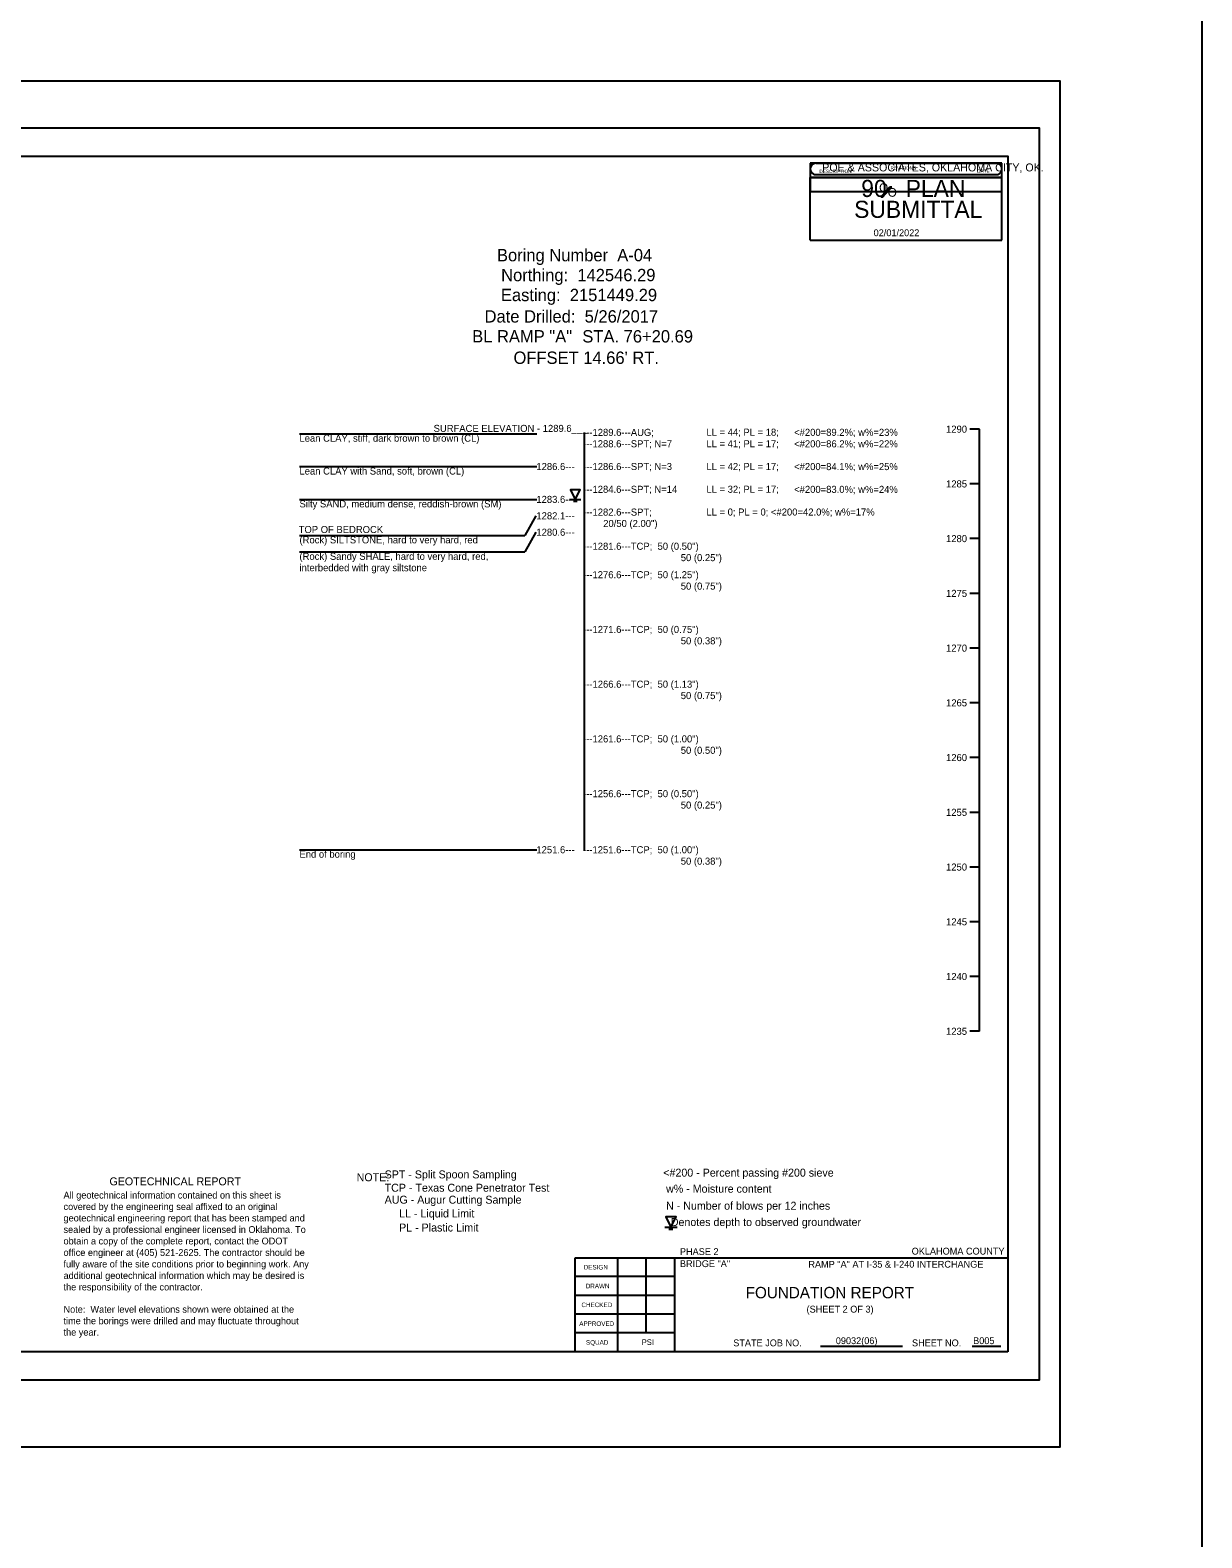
# Model space of a CAD drawing. Extents: x 2150161.5 to 2150203.1, y 143779.5 to 143868.5.
# Drawn here: x 2150182.49 to 2150203.07, y 143808.09 to 143834.58 of the extents above; entities that cross this region are included whole.
import ezdxf

# ---------------------------------------------------------------- set-up
doc = ezdxf.new("R2010")
doc.units = 0
for name, color, linetype in [('Default', 7, 'Continuous'), ('S', 7, 'Continuous'), ('SHT_Plot_Shape_Full', 7, 'Continuous'), ('SHT_Plot_Shape_Half', 7, 'Continuous'), ('SHT_Sheet_Border', 7, 'Continuous'), ('SHT_Stamp_90_Submit', 7, 'Continuous'), ('SHT_Stamp_Rev_Block', 7, 'Continuous'), ('SHT_Standard_Sheet_Lines', 7, 'Continuous'), ('SHT_Standard_Sheet_Txt', 7, 'Continuous'), ('T', 7, 'Continuous'), ('T-Title', 7, 'Continuous'), ('Text', 7, 'Continuous')]:
    doc.layers.add(name, color=color, linetype=linetype)

# ---------------------------------------------------------------- blocks, each defined once
blk = doc.blocks.new('DGRFC_WTLEV1')
at = {"layer": 'Default'}
for points in [[(-0.0127, 0), (0.0127, 0)], [(0, 0), (0.0106, 0.0212), (-0.0106, 0.0212), (0, 0)], [(-0.0042, -0.0042), (0.0042, -0.0042)]]:
    blk.add_lwpolyline(points, dxfattribs=at)

msp = doc.modelspace()

# ---------------------------------------------------------------- linework, layer by layer
at = {"layer": 'Default'}
for p, q in [((2150199.164, 143816.992), (2150199.164, 143827.569)), ((2150191.371, 143826.046), (2150191.182, 143825.702)), ((2150191.371, 143825.758), (2150191.182, 143825.414))]:
    msp.add_line(p, q, dxfattribs=at)
for points in [[(2150199.164, 143827.569), (2150198.997, 143827.569)], [(2150187.222, 143827.489), (2150191.388, 143827.489)], [(2150192.221, 143827.507), (2150192.221, 143820.172)], [(2150187.222, 143826.912), (2150191.388, 143826.912)], [(2150199.164, 143826.607), (2150198.997, 143826.607)], [(2150187.222, 143826.335), (2150191.388, 143826.335)], [(2150187.222, 143825.702), (2150191.182, 143825.702)], [(2150199.164, 143825.646), (2150198.997, 143825.646)], [(2150187.222, 143825.414), (2150191.182, 143825.414)], [(2150199.164, 143824.684), (2150198.997, 143824.684)], [(2150199.164, 143823.723), (2150198.997, 143823.723)], [(2150199.164, 143822.761), (2150198.997, 143822.761)], [(2150199.164, 143821.8), (2150198.997, 143821.8)], [(2150199.164, 143820.838), (2150198.997, 143820.838)], [(2150187.222, 143820.181), (2150191.388, 143820.181)], [(2150199.164, 143819.877), (2150198.997, 143819.877)], [(2150199.164, 143818.915), (2150198.997, 143818.915)], [(2150199.164, 143818.915), (2150198.997, 143818.915)], [(2150199.164, 143817.954), (2150198.997, 143817.954)], [(2150199.164, 143817.954), (2150198.997, 143817.954)], [(2150199.164, 143816.992), (2150198.997, 143816.992)], [(2150199.164, 143816.992), (2150198.997, 143816.992)]]:
    msp.add_lwpolyline(points, dxfattribs=at)
at = {"layer": 'S'}
msp.add_lwpolyline([(2150161.53, 143868.477), (2150203.071, 143868.477), (2150203.071, 143779.536), (2150161.53, 143779.536)], close=True, dxfattribs=at)
at = {"layer": 'SHT_Plot_Shape_Full'}
msp.add_lwpolyline([(2150164.575, 143833.688), (2150200.575, 143833.688), (2150200.575, 143809.688), (2150164.575, 143809.688)], close=True, dxfattribs=at)
at = {"layer": 'SHT_Plot_Shape_Half'}
msp.add_lwpolyline([(2150166.212, 143832.863), (2150200.212, 143832.863), (2150200.212, 143810.863), (2150166.212, 143810.863)], close=True, dxfattribs=at)
at = {"layer": 'SHT_Sheet_Border'}
for p, q in [((2150192.062, 143811.363), (2150192.062, 143813.013)), ((2150192.062, 143813.013), (2150199.662, 143813.013)), ((2150193.812, 143811.363), (2150193.812, 143813.014))]:
    msp.add_line(p, q, dxfattribs=at)
msp.add_lwpolyline([(2150199.662, 143811.363), (2150168.162, 143811.363), (2150168.162, 143832.363), (2150199.662, 143832.363)], close=True, dxfattribs=at)
at = {"layer": 'SHT_Stamp_90_Submit'}
for p, q in [((2150196.293, 143832.239), (2150199.459, 143832.239)), ((2150196.193, 143831.989), (2150199.559, 143831.989)), ((2150196.193, 143830.889), (2150196.193, 143831.989)), ((2150196.293, 143832.039), (2150199.459, 143832.039)), ((2150197.437, 143831.65), (2150197.592, 143831.823)), ((2150197.454, 143831.65), (2150197.61, 143831.823)), ((2150197.459, 143831.65), (2150197.615, 143831.823)), ((2150197.467, 143831.65), (2150197.623, 143831.823)), ((2150197.592, 143831.823), (2150197.623, 143831.823)), ((2150199.559, 143830.889), (2150199.559, 143831.989)), ((2150197.437, 143831.65), (2150197.467, 143831.65)), ((2150196.193, 143830.889), (2150199.559, 143830.889))]:
    msp.add_line(p, q, dxfattribs=at)
for centre, start, end in [((2150196.294, 143832.139), 89.9952, 270), ((2150199.46, 143832.139), 270, 90.0048)]:
    msp.add_arc(centre, 0.1, start, end, dxfattribs=at)
at = {"layer": 'SHT_Stamp_Rev_Block'}
for p, q in [((2150196.194, 143832.239), (2150196.194, 143831.739)), ((2150199.559, 143832.239), (2150196.194, 143832.239)), ((2150199.559, 143831.739), (2150199.559, 143832.239)), ((2150199.559, 143831.989), (2150196.194, 143831.989)), ((2150199.559, 143831.739), (2150196.194, 143831.739))]:
    msp.add_line(p, q, dxfattribs=at)
at = {"layer": 'SHT_Standard_Sheet_Lines'}
for p, q in [((2150192.812, 143811.363), (2150192.812, 143813.014)), ((2150193.312, 143811.693), (2150193.312, 143813.014)), ((2150196.373, 143811.459), (2150197.813, 143811.459)), ((2150199.038, 143811.459), (2150199.54, 143811.459))]:
    msp.add_line(p, q, dxfattribs=at)
for points in [[(2150193.812, 143812.683), (2150192.062, 143812.683)], [(2150193.812, 143812.353), (2150192.062, 143812.353)], [(2150193.812, 143812.023), (2150192.062, 143812.023)], [(2150193.812, 143811.693), (2150192.062, 143811.693)]]:
    msp.add_lwpolyline(points, dxfattribs=at)

# ---------------------------------------------------------------- block references
at = {"layer": 'Default'}
for p, xscale, yscale in [((2150192.066, 143826.335), 7.873999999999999, 7.873999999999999), ((2150193.745, 143813.553), 8.503919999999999, 8.503919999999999)]:
    msp.add_blockref('DGRFC_WTLEV1', p, dxfattribs=dict(at, xscale=xscale, yscale=yscale))

# ---------------------------------------------------------------- texts
for s, height, p in [('Boring Number  A-04', 0.217, (2150190.691, 143830.517)), ('Northing:  142546.29', 0.217, (2150190.764, 143830.167)), ('Easting:  2151449.29', 0.217, (2150190.76, 143829.817)), ('Date Drilled:  5/26/2017', 0.217, (2150190.473, 143829.441)), ('BL RAMP "A" ', 0.217, (2150190.256, 143829.091)), ('STA. 76+20.69', 0.217, (2150192.19, 143829.091)), ("OFFSET 14.66' RT.", 0.217, (2150190.981, 143828.715)), ('SURFACE ELEVATION - 1289.6___', 0.124, (2150189.578, 143827.52)), ('---1289.6---AUG;', 0.124, (2150192.203, 143827.45)), ('LL = 44; PL = 18;', 0.124, (2150194.369, 143827.453)), ('<#200=89.2%; w%=23%', 0.124, (2150195.91, 143827.451)), ('Lean CLAY, stiff, dark brown to brown (CL)', 0.124, (2150187.222, 143827.348)), ('---1288.6---SPT; N=7', 0.124, (2150192.203, 143827.25)), ('LL = 41; PL = 17;', 0.124, (2150194.369, 143827.251)), ('<#200=86.2%; w%=22%', 0.124, (2150195.91, 143827.249)), ('Lean CLAY with Sand, soft, brown (CL)', 0.124, (2150187.222, 143826.771)), ('1286.6---', 0.124, (2150191.383, 143826.85)), ('---1286.6---SPT; N=3', 0.124, (2150192.203, 143826.85)), ('LL = 42; PL = 17;', 0.124, (2150194.369, 143826.851)), ('<#200=84.1%; w%=25%', 0.124, (2150195.91, 143826.849)), ('---1284.6---SPT; N=14', 0.124, (2150192.203, 143826.45)), ('LL = 32; PL = 17;', 0.124, (2150194.369, 143826.451)), ('<#200=83.0%; w%=24%', 0.124, (2150195.91, 143826.449)), ('Silty SAND, medium dense, reddish-brown (SM)', 0.124, (2150187.222, 143826.194)), ('1283.6---', 0.124, (2150191.383, 143826.273)), ('1282.1---', 0.124, (2150191.383, 143825.985)), ('---1282.6---SPT;', 0.124, (2150192.203, 143826.05)), ('20/50 (2.00")', 0.124, (2150192.557, 143825.85)), ('LL = 0; PL = 0; <#200=42.0%%%; w%%%=17%%%', 0.124, (2150194.369, 143826.051)), ('TOP OF BEDROCK', 0.124, (2150187.208, 143825.744)), ('1280.6---', 0.124, (2150191.383, 143825.696)), ('(Rock) SILTSTONE, hard to very hard, red', 0.124, (2150187.222, 143825.562)), ('---1281.6---TCP;  50 (0.50")', 0.124, (2150192.203, 143825.45)), ('(Rock) Sandy SHALE, hard to very hard, red,', 0.124, (2150187.222, 143825.273)), ('interbedded with gray siltstone', 0.124, (2150187.222, 143825.073)), ('50 (0.25")', 0.124, (2150193.919, 143825.25)), ('---1276.6---TCP;  50 (1.25")', 0.124, (2150192.203, 143824.95)), ('50 (0.75")', 0.124, (2150193.919, 143824.75)), ('---1271.6---TCP;  50 (0.75")', 0.124, (2150192.203, 143823.989)), ('50 (0.38")', 0.124, (2150193.919, 143823.789)), ('---1266.6---TCP;  50 (1.13")', 0.124, (2150192.203, 143823.027)), ('50 (0.75")', 0.124, (2150193.919, 143822.827)), ('---1261.6---TCP;  50 (1.00")', 0.124, (2150192.203, 143822.066)), ('50 (0.50")', 0.124, (2150193.919, 143821.866)), ('---1256.6---TCP;  50 (0.50")', 0.124, (2150192.203, 143821.104)), ('50 (0.25")', 0.124, (2150193.919, 143820.904)), ('End of boring', 0.124, (2150187.222, 143820.041)), ('1251.6---', 0.124, (2150191.383, 143820.119)), ('---1251.6---TCP;  50 (1.00")', 0.124, (2150192.203, 143820.119)), ('50 (0.38")', 0.124, (2150193.919, 143819.919))]:
    msp.add_text(s, height=height, dxfattribs=at).set_placement(p)
for s, p in [('1290', (2150198.578, 143827.507)), ('1285', (2150198.578, 143826.545)), ('1280', (2150198.578, 143825.584)), ('1275', (2150198.578, 143824.622)), ('1270', (2150198.578, 143823.661)), ('1265', (2150198.578, 143822.699)), ('1260', (2150198.578, 143821.738)), ('1255', (2150198.578, 143820.776)), ('1250', (2150198.578, 143819.815)), ('1245', (2150198.578, 143818.853)), ('1240', (2150198.578, 143817.892)), ('1235', (2150198.578, 143816.93))]:
    msp.add_text(s, height=0.124, rotation=0.0001, dxfattribs=at).set_placement(p)
at = {"layer": 'SHT_Stamp_90_Submit'}
for s, height, p in [('POE & ASSOCIATES, OKLAHOMA CITY, OK.', 0.14, (2150196.403, 143832.096)), ('90   PLAN', 0.3, (2150197.089, 143831.647)), ('O', 0.153, (2150197.402, 143831.735)), ('O', 0.153, (2150197.554, 143831.651)), ('SUBMITTAL', 0.3, (2150196.964, 143831.28)), ('02/01/2022', 0.12, (2150197.306, 143830.958))]:
    msp.add_text(s, height=height, dxfattribs=at).set_placement(p)
at = {"layer": 'SHT_Stamp_Rev_Block'}
for s, height, p in [('DESCRIPTION', 0.05999, (2150196.353, 143832.067)), ('REVISIONS', 0.06, (2150197.602, 143832.126)), ('DATE', 0.06, (2150199.123, 143832.071))]:
    msp.add_text(s, height=height, dxfattribs=at).set_placement(p)
at = {"layer": 'SHT_Standard_Sheet_Txt'}
for s, height, p in [('DESIGN', 0.08, (2150192.215, 143812.808)), ('DRAWN', 0.08, (2150192.25, 143812.478)), ('CHECKED', 0.08, (2150192.175, 143812.147)), ('APPROVED', 0.08, (2150192.136, 143811.817)), ('SQUAD', 0.08, (2150192.254, 143811.487)), ('STATE JOB NO.', 0.12, (2150194.84, 143811.459)), ('SHEET NO. ', 0.12, (2150197.98, 143811.459))]:
    msp.add_text(s, height=height, dxfattribs=at).set_placement(p)
at = {"layer": 'T'}
for s, height, p in [('PHASE 2', 0.12, (2150193.904, 143813.062)), ('OKLAHOMA COUNTY', 0.12, (2150197.974, 143813.07)), ('BRIDGE "A"', 0.12, (2150193.904, 143812.85)), ('RAMP "A" AT I-35 & I-240 INTERCHANGE', 0.12, (2150196.16, 143812.84)), ('(SHEET 2 OF 3)', 0.12, (2150196.128, 143812.051)), ('PSI', 0.1, (2150193.232, 143811.481)), ('09032(06)', 0.12, (2150196.642, 143811.497)), ('B005', 0.12, (2150199.054, 143811.497))]:
    msp.add_text(s, height=height, dxfattribs=at).set_placement(p)
at = {"layer": 'T-Title'}
msp.add_text('FOUNDATION REPORT', height=0.2, dxfattribs=at).set_placement((2150195.059, 143812.302))
at = {"layer": 'Text'}
for s, height, p in [('GEOTECHNICAL REPORT', 0.14, (2150183.885, 143814.286)), ('NOTE:', 0.14, (2150188.226, 143814.358)), ('    SPT - Split Spoon Sampling', 0.14, (2150188.51, 143814.408)), (' <#200 - Percent passing #200 sieve', 0.14, (2150193.56, 143814.439)), ('All geotechnical information contained on this sheet is ', 0.12, (2150183.078, 143814.054)), ('    AUG - Augur Cutting Sample', 0.14, (2150188.51, 143813.964)), ('    TCP - Texas Cone Penetrator Test', 0.14, (2150188.51, 143814.174)), ('w% - Moisture content', 0.14, (2150193.661, 143814.157)), ('covered by the engineering seal affixed to an original ', 0.12, (2150183.078, 143813.852)), (' LL - Liquid Limit', 0.14, (2150188.92, 143813.722)), ('N - Number of blows per 12 inches', 0.14, (2150193.661, 143813.858)), ('sealed by a professional engineer licensed in Oklahoma. To ', 0.12, (2150183.078, 143813.45)), ('geotechnical engineering report that has been stamped and ', 0.12, (2150183.078, 143813.652)), (' PL - Plastic Limit', 0.14, (2150188.92, 143813.475)), ('    Denotes depth to observed groundwater', 0.14, (2150193.536, 143813.571)), ('obtain a copy of the complete report, contact the ODOT ', 0.12, (2150183.078, 143813.248)), ('office engineer at (405) 521-2625. The contractor should be ', 0.12, (2150183.078, 143813.046)), ('fully aware of the site conditions prior to beginning work. Any ', 0.12, (2150183.078, 143812.844)), ('additional geotechnical information which may be desired is ', 0.12, (2150183.078, 143812.642)), ('the responsibility of the contractor.', 0.12, (2150183.078, 143812.44)), ('time the borings were drilled and may fluctuate throughout ', 0.12, (2150183.078, 143811.846)), ('Note:  Water level elevations shown were obtained at the ', 0.12, (2150183.078, 143812.048)), ('the year.', 0.12, (2150183.078, 143811.646))]:
    msp.add_text(s, height=height, dxfattribs=at).set_placement(p)

doc.saveas('drawing.dxf')
